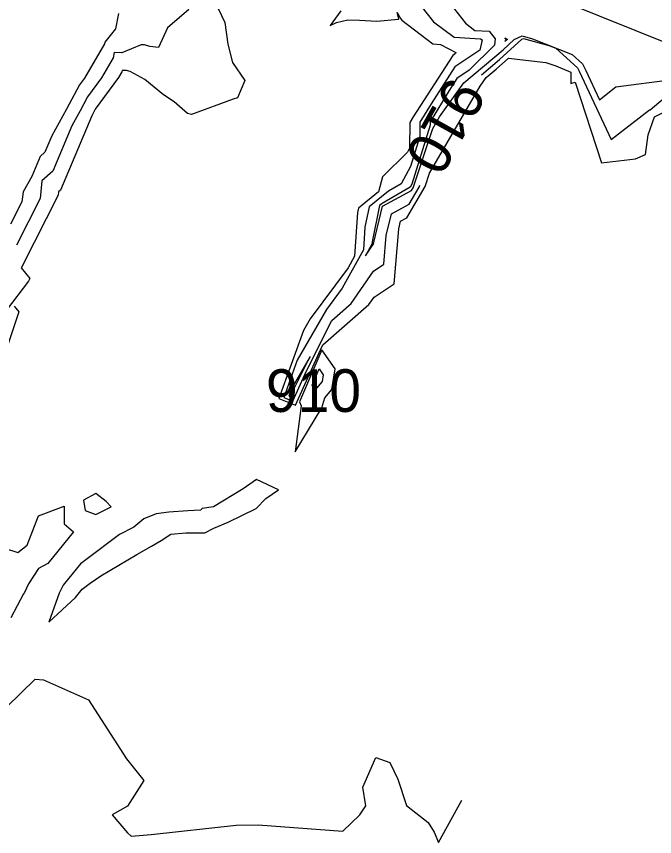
# Model space of a CAD drawing. Extents: x 1368651 to 1378602, y 762048 to 779328.
# Drawn here: x 1377179.9 to 1377329.5, y 762773.1 to 762965.4 of the extents above; entities that cross this region are included whole.
import ezdxf

# ---------------------------------------------------------------- set-up
doc = ezdxf.new("R2010")
doc.units = 0
for name, color, linetype in [('DTM Contours Major', 7, 'Continuous'), ('DTM Contours Major Text', 7, 'Continuous'), ('DTM Contours Minor', 7, 'Continuous'), ('Prop Erosion Rip Rap Class I Label', 7, 'Continuous')]:
    doc.layers.add(name, color=color, linetype=linetype)

msp = doc.modelspace()

# ---------------------------------------------------------------- linework, layer by layer
at = {"layer": 'DTM Contours Major'}
for points in [[(1377272.37, 762970.94), (1377277.69, 762964.13), (1377282.46, 762960.51), (1377288.65, 762960.11), (1377289.04, 762959.9), (1377288.5, 762957.46), (1377282.66, 762953.53), (1377277.11, 762944.92), (1377274.47, 762940.58), (1377274.44, 762937.21), (1377272.26, 762930.18), (1377270.07, 762926.16), (1377267.1, 762924.44), (1377262.54, 762920.76), (1377261.57, 762915.98), (1377261.21, 762910.64), (1377256.26, 762901.65), (1377252.55, 762896.65), (1377245.7, 762884.75), (1377242.56, 762876.03), (1377244.69, 762875.2), (1377247.88, 762882.29), (1377253.79, 762894.09), (1377258.32, 762898.05), (1377263.6, 762905.68), (1377266.04, 762907.27), (1377266.59, 762913.98), (1377267.81, 762919.13), (1377271.94, 762921.35), (1377274.3, 762925.37), (1377274.43, 762925.78)], [(1377288.89, 762951.7), (1377293.15, 762955.27), (1377298.34, 762960.03), (1377298.76, 762960.22), (1377304.68, 762958.6), (1377306.32, 762957.94), (1377311.42, 762953.32), (1377311.82, 762952.58), (1377319.33, 762936.52), (1377328.3, 762943.49), (1377328.47, 762943.51), (1377340.03, 762953.24)], [(1377249.74, 762877.64), (1377249.18, 762878.88), (1377250.82, 762882.75), (1377251.81, 762881.32), (1377251.58, 762879.8), (1377249.74, 762877.64)]]:
    msp.add_lwpolyline(points, dxfattribs=at)
at = {"layer": 'DTM Contours Minor'}
for points in [[(1377274.85, 762977), (1377285.17, 762963.78), (1377287.38, 762962.1), (1377290.73, 762961.89), (1377292.12, 762960.1), (1377291.98, 762958.61), (1377285.99, 762952.77), (1377283.16, 762950.86), (1377281.3, 762947.98), (1377276.88, 762940.7), (1377276.87, 762939.91), (1377272.55, 762926.01), (1377272.19, 762925.34), (1377265.6, 762921.53), (1377265.03, 762921.07), (1377263.31, 762912.51), (1377263.28, 762912.14), (1377261.7, 762909.25), (1377263.45, 762911.79), (1377263.62, 762911.9), (1377263.66, 762912.37), (1377265.69, 762920.87), (1377272.5, 762924.53), (1377272.9, 762925.21), (1377277.49, 762939.13), (1377279.07, 762941.83), (1377284.75, 762949.83), (1377293.97, 762957.56), (1377296.59, 762959.97), (1377298.45, 762960.8), (1377300.87, 762960.14), (1377310.15, 762956.43), (1377312.55, 762954.25), (1377313.37, 762952.73), (1377316.59, 762945.86), (1377320.43, 762948.84), (1377333.61, 762950.58)], [(1377227.2, 762967.21), (1377228.72, 762963.96), (1377229.43, 762958.84), (1377230.52, 762954.61), (1377233.43, 762950.37), (1377231.69, 762946.33), (1377230.72, 762946), (1377220.93, 762942.4), (1377219.99, 762942.64), (1377216.85, 762945.35), (1377214.34, 762946.98), (1377209.98, 762950.56), (1377206.5, 762952.45), (1377205.69, 762952.71), (1377204.64, 762952.73), (1377204.57, 762952.38), (1377203.79, 762951.05), (1377198.35, 762943.62), (1377197.96, 762942.88), (1377197.52, 762942.09), (1377190.19, 762924.66), (1377189.73, 762924.24), (1377189.65, 762923.49), (1377181.2, 762906.81), (1377180.98, 762906.39), (1377182.98, 762903.89), (1377182.68, 762903.27), (1377177.44, 762896.44)], [(1377203.82, 762966.09), (1377203.07, 762962.5), (1377200.59, 762959.31), (1377200.51, 762958.95), (1377195.8, 762950.91), (1377194.68, 762949.38), (1377191.64, 762943.61), (1377188.2, 762937.42), (1377186.56, 762933.52), (1377185.46, 762932.53), (1377183.46, 762927.81), (1377181.42, 762924.22), (1377181.17, 762921.9), (1377178.52, 762916.67)], [(1377220.28, 762967.01), (1377215.31, 762962.67), (1377213.2, 762958.07), (1377211.18, 762958.36), (1377209.91, 762958.71), (1377209.12, 762958.69), (1377204.61, 762956.86), (1377202.79, 762956.91), (1377202.54, 762955.67), (1377199.79, 762950.98), (1377196.51, 762946.5), (1377194.8, 762943.25), (1377192.86, 762939.76), (1377188.38, 762929.09), (1377185.85, 762926.82), (1377185.41, 762922.7), (1377179.86, 762911.74)], [(1377255.91, 762966.66), (1377253.45, 762963.29), (1377254.93, 762963.98), (1377257.56, 762964.58), (1377260.3, 762964.48), (1377264.35, 762964.27), (1377269.41, 762964.76), (1377269.54, 762964.84), (1377269.14, 762966.3), (1377269.9, 762964.88), (1377270.2, 762964.49), (1377277.53, 762958.92), (1377279.32, 762958.8), (1377282.9, 762956.93), (1377282.83, 762956.65), (1377282.15, 762956.19), (1377272.92, 762941.86), (1377272.07, 762940.47), (1377272.02, 762934.52), (1377271.97, 762934.36), (1377271.54, 762933.58), (1377265.66, 762927.76), (1377264.73, 762924.24), (1377260.04, 762920.45), (1377259.84, 762919.44), (1377259.13, 762909.15), (1377257.62, 762906.39), (1377248.76, 762894.47), (1377247.16, 762891.7), (1377241.41, 762875.75), (1377245.31, 762874.22), (1377251.15, 762887.19), (1377251.73, 762888.36), (1377262.53, 762897.81), (1377263.75, 762899.58), (1377268.45, 762902.65), (1377269.51, 762915.6), (1377269.94, 762917.4), (1377271.39, 762918.18), (1377275.71, 762925.54), (1377276.73, 762928.64), (1377288.61, 762949.06), (1377290.03, 762951.06), (1377292.32, 762952.98), (1377295.2, 762955.62), (1377303.95, 762954.59), (1377306.32, 762953.8), (1377309.85, 762952.33), (1377309.88, 762949.62), (1377310.88, 762949.93), (1377317.06, 762931.08), (1377324.98, 762931.96), (1377327.36, 762933.03), (1377327.98, 762937.62), (1377329.43, 762941.82), (1377335.89, 762945.04)], [(1377294.39, 762960.38), (1377295.03, 762959.98), (1377294.85, 762959.9), (1377294.79, 762959.85), (1377294.35, 762959.48), (1377294.75, 762959.87), (1377294.76, 762959.9), (1377294.39, 762960.38)], [(1377179.37, 762897.46), (1377180.4, 762896.11), (1377176.61, 762884.61)], [(1377251.44, 762887.23), (1377246.24, 762874.99), (1377246.65, 762874.08), (1377245.22, 762863.27), (1377251.46, 762873.6), (1377252.19, 762875.96), (1377253.85, 762877.9), (1377254.58, 762882.71), (1377251.44, 762887.23)], [(1377248.76, 762885.65), (1377244.24, 762877.8), (1377243.71, 762876.32), (1377244.07, 762876.17), (1377244.61, 762877.38), (1377248.76, 762885.65)], [(1377241.3, 762854.36), (1377236.13, 762856.76), (1377233.06, 762854.61), (1377226.06, 762850.41), (1377223.39, 762849.96), (1377223, 762849.63), (1377220.09, 762849.43), (1377215.58, 762849.15), (1377212.6, 762848.72), (1377209.77, 762847.58), (1377207.42, 762845.6), (1377204.03, 762843.91), (1377196.16, 762837.97), (1377194.88, 762837.03), (1377192.18, 762833.68), (1377190.85, 762832.04), (1377189.87, 762830.17), (1377187.44, 762823.33), (1377193.69, 762829.14), (1377195.31, 762831.08), (1377197.14, 762832.52), (1377199.68, 762834.24), (1377208.11, 762839.24), (1377211.55, 762841.17), (1377213.79, 762842.48), (1377216.04, 762843.97), (1377219.57, 762844.26), (1377224.02, 762844.3), (1377226.18, 762845.39), (1377229.5, 762846.82), (1377236.09, 762850.02), (1377238.31, 762852.34), (1377241.3, 762854.36)], [(1377200.9, 762851.66), (1377198.52, 762853.51), (1377195.62, 762851.96), (1377196, 762849.52), (1377198.51, 762848.61), (1377202.05, 762850.38), (1377200.9, 762851.66)], [(1377177.05, 762840.69), (1377180.18, 762839.68), (1377182.41, 762841.42), (1377185.08, 762848.3), (1377191.06, 762850.58), (1377191.03, 762846.43), (1377193.25, 762844.5), (1377187.27, 762837.06), (1377185.08, 762835.91), (1377182.74, 762832.36), (1377181.75, 762830.28), (1377181.54, 762830.01), (1377178.55, 762824.34)], [(1377177.63, 762803.47), (1377184.3, 762809.98), (1377186.2, 762809.82), (1377196.74, 762805.11), (1377205.67, 762791.31), (1377209.73, 762786.18), (1377205.92, 762780.18), (1377202.34, 762778.19), (1377205.89, 762773.93), (1377206.79, 762773.17), (1377211.46, 762773.57), (1377231.42, 762775.77), (1377236.52, 762775.84), (1377256.43, 762774.3), (1377260.4, 762778.15), (1377261.78, 762780.29), (1377261.06, 762784.66), (1377264.14, 762791.59), (1377267.41, 762790.47), (1377269.26, 762786.52), (1377271.36, 762780.33), (1377276.42, 762776.4), (1377277.84, 762774.11), (1377278.83, 762771.66), (1377284.27, 762781.61)]]:
    msp.add_lwpolyline(points, dxfattribs=at)
at = {"layer": 'Prop Erosion Rip Rap Class I Label'}
msp.add_lwpolyline([(1377248.45, 762992.92), (1377427.12, 762921.08), (1377430.32, 762927.02)], dxfattribs=at)

# ---------------------------------------------------------------- texts
at = {"layer": 'DTM Contours Major Text'}
msp.add_text('910', height=10, rotation=240.8594, dxfattribs=at).set_placement((1377281.54, 762951.84))
msp.add_text('910', height=10, dxfattribs=at).set_placement((1377238.36, 762872.64))

doc.saveas('drawing.dxf')
